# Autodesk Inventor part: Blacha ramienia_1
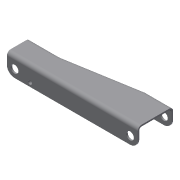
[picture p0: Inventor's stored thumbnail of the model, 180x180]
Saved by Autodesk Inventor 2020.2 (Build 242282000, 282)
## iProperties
Created: 2005-10
Part Number: Blacha ramienia_1
Document SubType Name: Modeling
Designer: F.Stasiak
Stock Number: Blacha ramienia_1
Material: Ogólny
Density: 1 g/cm^3
Appearance: Domyślna
Manager: www.cadconsulting.pl
Company: Fabian Stasiak CAD Consulting
Author: F.Stasiak
Subject: Zbiór ćwiczeń. Autodesk Inventor 2020. Kurs podstawowy
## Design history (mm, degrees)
sketch "Szkic1"
  geometry: L1 (-1300, -230)-(0, -230); L2 (0, -230)-(0, 230); L3 (0, 230)-(-350, 230); L4 (-350, 230)-(-1300, 70); L5 (-1300, 70)-(-1300, -230); 2 further points
  constraints: 10 end point, 2 perpendicular, 1 coincident, 1 horizontal, 1 midpoint, 1 parallel
  dimensions: "d0" = 1300 distance of L1.start L1.end; "d1" = 460 distance of L1.end L2.end; "d2" = 300 distance of L4.end L1.start; "d3" = 350 distance of L2.end L3.end
extrude "Wyciągnięcie proste1" new body sketch "Szkic1" distance "d4" = 250; taper "d5" = 0 deg
sketch "Szkic3"
  geometry: L1 (250, 0)-(250, 300) reference; L2 (0, 300)-(250, 300) reference; L3 (0, 300)-(0, 0) reference; L4 (0, 0)-(250, 0) reference
extrude "Wyciągnięcie proste2" join sketch "Szkic3" distance "d7" = 400; taper "d8" = 0 deg
fillet "Zaokrąglenie6" dims "d29" = 100
fillet "Zaokrąglenie7" dims "d30" = 50
feature "Skorupa1" dims "d12" = 20
fillet "Zaokrąglenie4" dims "d13" = 100
sketch "Szkic6"
  geometry: L1 (100, -100)-(300, -100); A1 r 100 centre (1600, -100) between (1600, -200) and (1700, -100) reference; A2 r 100 centre (100, -100) between (0, -100) and (100, -200) reference
  constraints: 2 end point, 1 horizontal
  dimensions: "d38" = 200 distance of L1.end L1.start
hole "Otwór3" sketch "Szkic6" at (100, -100), (1600, -100) diameter "d31" = 100; stored, may be unused: countersink angle "d35" = 90 deg, drill point angle "d37" = 118 deg; dims "d32" = 6, "d33" = 4, "d34" = 2, "d36" = 8
sketch "Szkic7"
  geometry: C1 r 50 at (100, -100) reference; 1 further point
  dimensions: "d47" = 50 vertical distance of point (300, -150) C1.centre; "d48" = 200 horizontal distance of point (300, -150) C1.centre
hole "Otwór4" sketch "Szkic7" at (300, -150) diameter "d40" = 50; stored, may be unused: countersink angle "d44" = 90 deg, drill point angle "d46" = 118 deg; dims "d41" = 6, "d42" = 4, "d43" = 2, "d45" = 8
sketch "Szkic8"
  geometry: C1 r 25 at (300, 150) reference; C2 r 45 at (300, 150)
  constraints: 1 centre point, 1 coincident
  dimensions: "d49" = 90 diameter of C2
extrude "Wyciągnięcie proste3" join sketch "Szkic8" distance "d50" = 30; taper "d51" = 0 deg
sketch "Szkic9"
  geometry: C1 r 25 at (300, -150) reference; C2 r 45 at (300, -150)
  constraints: 1 centre point, 1 coincident
  dimensions: "d52" = 90 diameter of C2
extrude "Wyciągnięcie proste4" join sketch "Szkic9" distance "d53" = 50; taper "d54" = 0 deg
node "Bryła1"
node "Korpusy bryłowe"
node "Korpusy powierzchniowe"
node "Pętla rzutowana2"
